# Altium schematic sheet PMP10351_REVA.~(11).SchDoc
size 431 x 279 mm; Date: Not shown in title block; ApprovedBy: Not shown in title block; CheckedBy: Not shown in title block; Author: Not shown in title block; CompanyName: Not shown in title block; Engineer: Not shown in title block; Organization: Not shown in title block; Address1: Not shown in title block; Address2: Not shown in title block; Address3: Not shown in title block; Address4: Not shown in title block; DocumentNumber: 1; Revision: Use project parameter SCH_Rev; SheetNumber: 1; SheetTotal: 1; PageSetup: Record=PageOptions|CenterHorizontal=True|CenterVertical=True|PrintScale=1.00|XCorrection=1.00|YCorrection=1.00|PrintKind=0|BorderSize=5000000|LeftOffset=0|BottomOffset=0|Orientation=2|PaperLength=1000|PaperWidth=1000|Scale=100|PaperSource=15|PrintQuality=600|MediaType=1|DitherType=10|PaperKind=Letter|PrintScaleMode=1
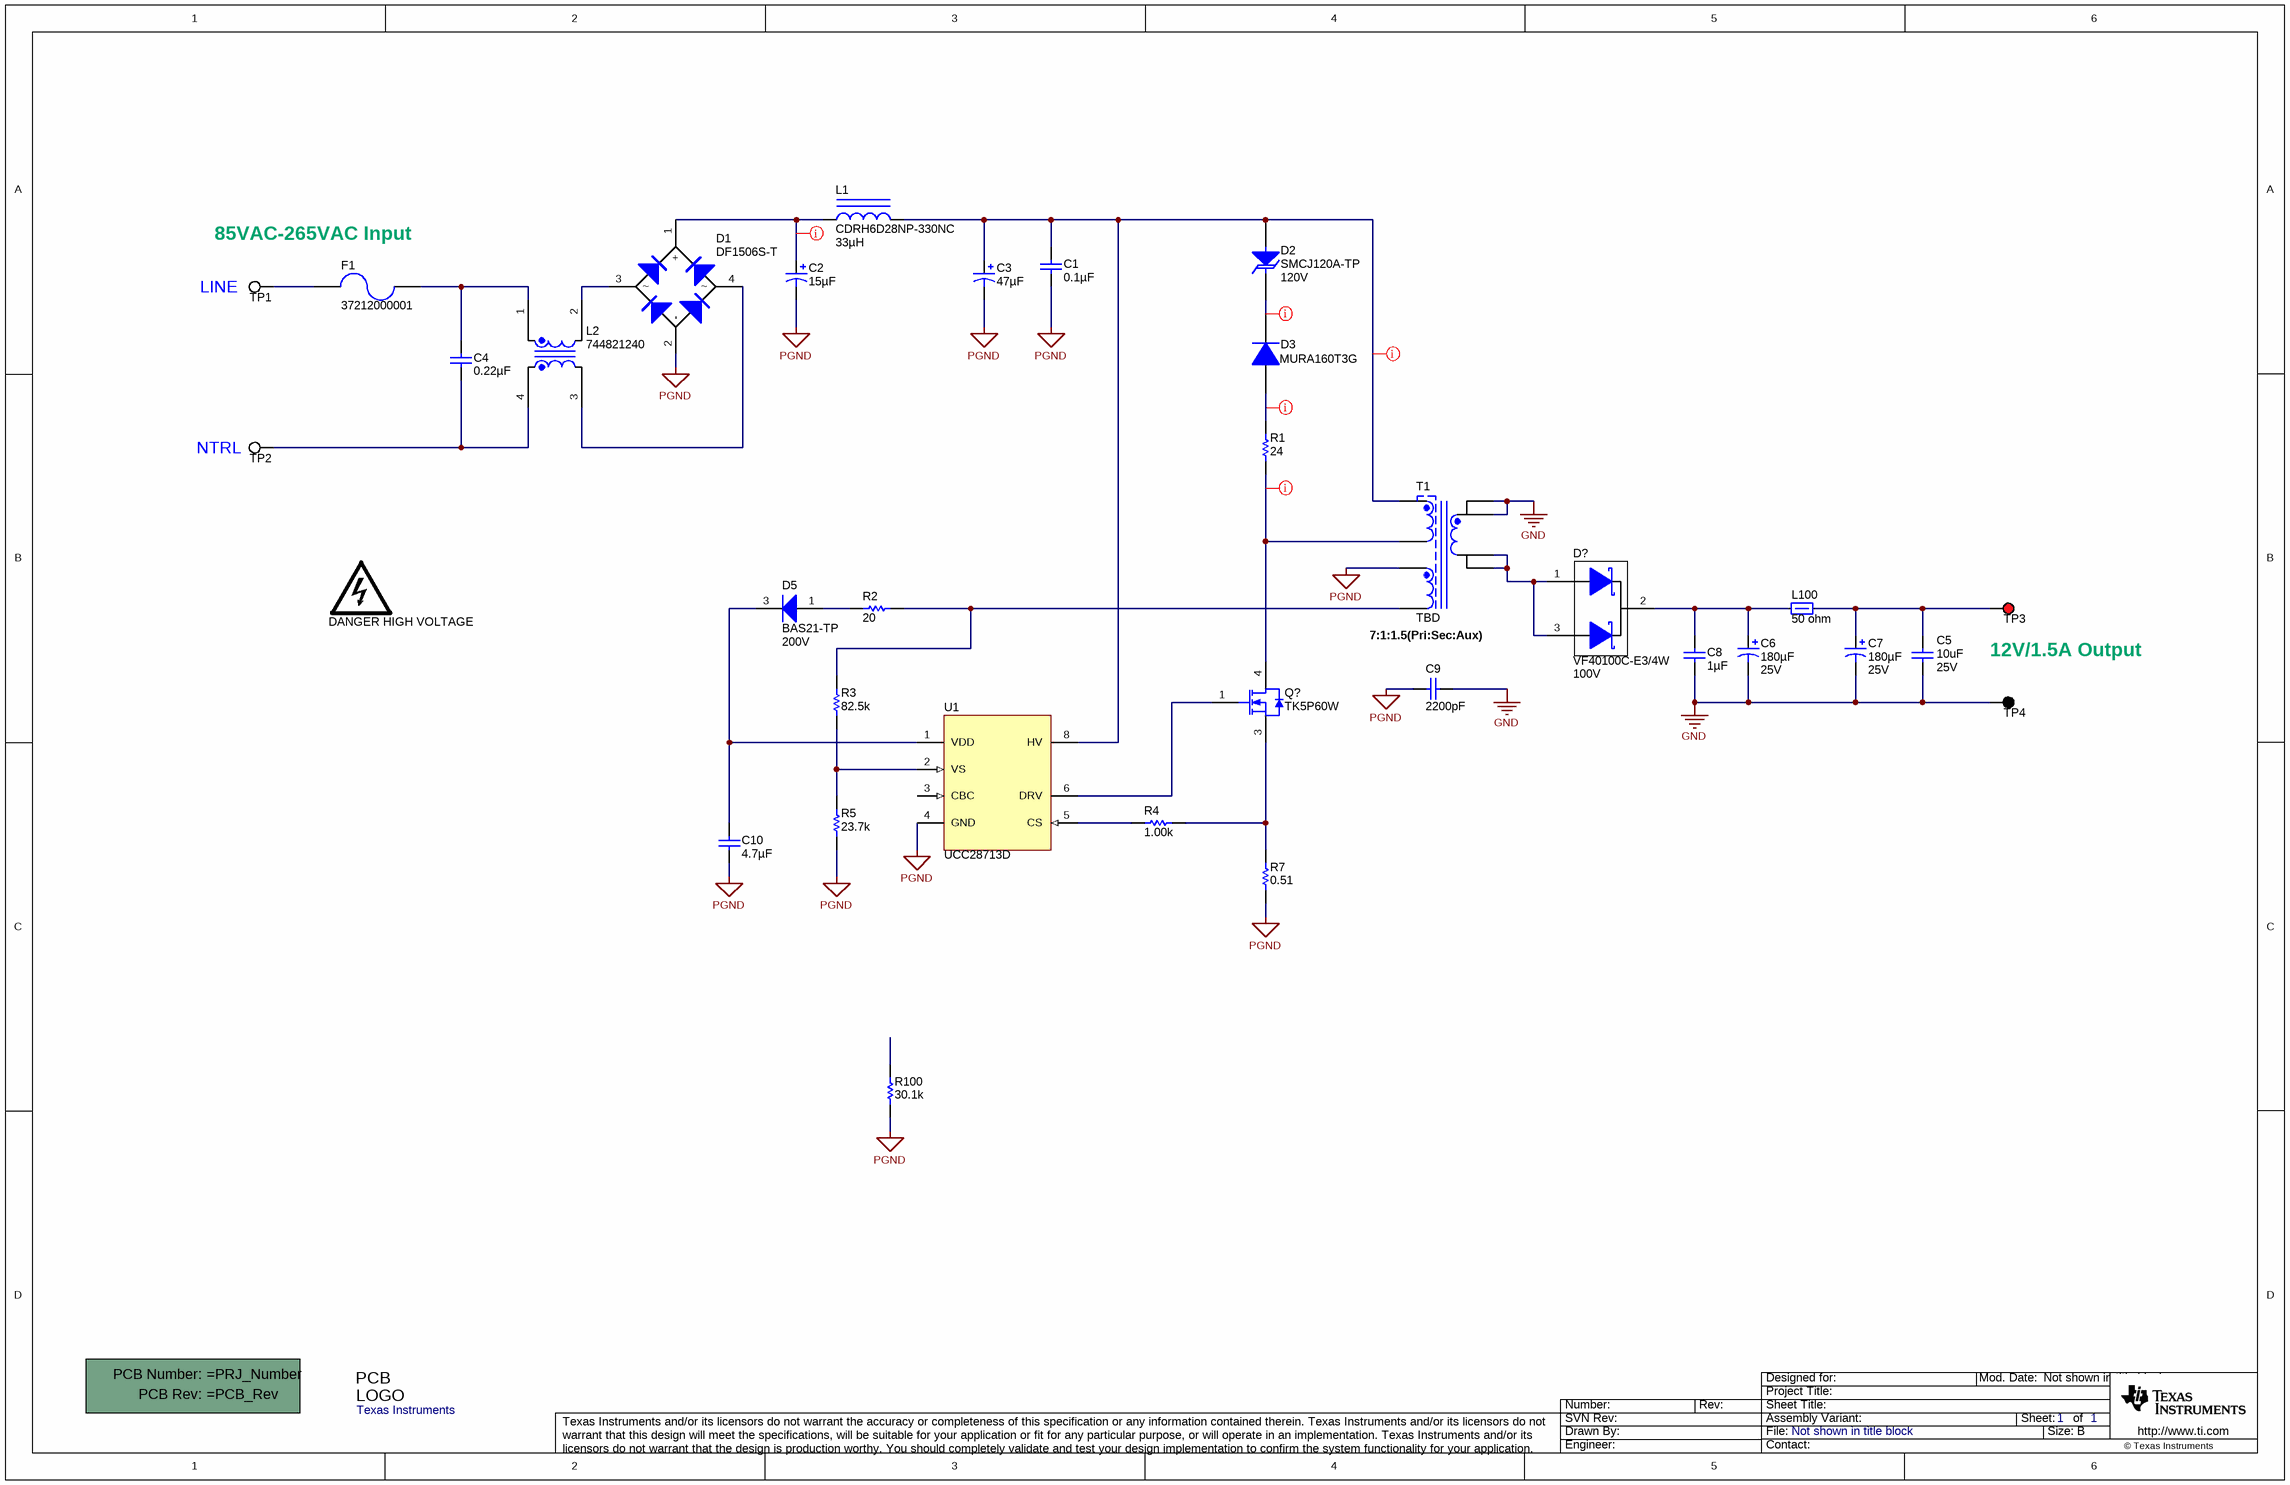
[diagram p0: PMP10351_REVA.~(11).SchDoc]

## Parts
(Parts that share a designator on the sheet are numbered #1, #2 ... from top to bottom, then left to right.)
!PCB  Printed Circuit Board  (value not drawn)  (mechanical)
C1  ValueDisplayed: 0.1µF  [1808_L]  (hidden comment: VJ1808Y104KXPAT5Z)
C2  ValueDisplayed: 15µF  [CAPPR5-12.5X20]  (hidden comment: EEUED2G150)
C3  ValueDisplayed: 47µF  [CAPPR7.5-18X20]  (hidden comment: EEUED2G470S)
C4  ValueDisplayed: 0.22µF  [B32922_12.5mm]  (hidden comment: B32922C3224M)
C5  value 10uF  Value2: 25V  [1206L]  (hidden comment: STD)
C6  ValueDisplayed: 180µF  Value2: 25V  [CAPPRD350W60D800H1150]  (hidden comment: 25SEPF180M)
C7  ValueDisplayed: 180µF  Value2: 25V  [CAPPRD350W60D800H1150]  (hidden comment: 25SEPF180M)
C8  ValueDisplayed: 1µF  [0603L]  (hidden comment: GRM188R61E105KA12D)
C9  ValueDisplayed: 2200pF  [CAPRD500W60D800H850]  (hidden comment: DE2E3KY222MA2BM01)
C10  ValueDisplayed: 4.7µF  [1206L]  (hidden comment: GRM319R61H475KA12)
D1  DF1506S-T  [DF-S]
D2  SMCJ120A-TP  value 120V  [SMC]
D3  MURA160T3G  [SMA]
D5  BAS21-TP  value 200V  [SOT-23L]
D?  VF40100C-E3/4W  value 100V  [TO-220AB]
F1  37212000001  [FUSE_372]
L1  CDRH6D28NP-330NC  ValueDisplayed: 33µH  [CDRH6D28]
L2  744821240  [WE-CMB_XS]
L100  value 50 ohm  [1206L]  (hidden comment: HI1206T500R-10)
LOGO1#1  DANGER HIGH VOLTAGE  [IEC_HighVoltage_Small]  (no BOM)
Logo1#2  Texas Instruments  [TI_Stacked_SolderMask_Small]  (no BOM)
Q?  TK5P60W  [DPAK]
R1  value 24  [2010L]  (hidden comment: CRCW201024R0JNEF)
R2  ValueDisplayed: 20  [0603L]  (hidden comment: CRCW060320R0JNEA)
R3  ValueDisplayed: 82.5k  [0402L]  (hidden comment: CRCW040282K5FKED)
R4  ValueDisplayed: 1.00k  [0402L]  (hidden comment: CRCW04021K00FKED)
R5  ValueDisplayed: 23.7k  [0402L]  (hidden comment: CRCW040223K7FKED)
R7  value 0.51  [0805L]  (hidden comment: CRM0805-FX-R510ELF)
R100  value 30.1k  [0603L]  (hidden comment: STD)
T1  TBD  [GCI_G134044LF]
TP1  5012  [Keystone5012]  (value not drawn)
TP2  5012  [Keystone5012]  (value not drawn)
TP3  5010  [Keystone5010]  (value not drawn)
TP4  5011  [Keystone5011]  (value not drawn)
U1  UCC28713D  [D0007A_L]

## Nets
GND: C5.2 C6.2(-) C7.2(-) C8.2 C9.1 T1.6 T1.7 TP4.1
PGND: C1.2 C2.2(-) C3.2(-) C9.2 C10.2 D1.2(-) R5.1 R7.1 R100.1 T1.1 U1.4(GND)
NetC1_1: C1.1 C3.1(+) D2.2(A) L1.2 T1.4 U1.8(HV)
NetC2_1: C2.1(+) D1.1(+) L1.1
NetC4_1: C4.1 F1.1 L2.1
NetC4_2: C4.2 L2.4 TP2.1
NetC5_1: C5.1 C7.1(+) L100.2 TP3.1
NetC6_1: C6.1(+) C8.1 D?.2(K) L100.1
NetC10_1: C10.1 D5.3(K) U1.1(VDD)
NetD1_3: D1.3 L2.2
NetD1_4: D1.4 L2.3
NetD2_1: D2.1(K) D3.1(K)
NetD3_2: D3.2(A) R1.2
NetD5_1: D5.1(A) R2.2
NetD?_1: D?.1(A) D?.3(A) T1.9 T1.10
NetF1_2: F1.2 TP1.1
NetQ?_1: Q?.1(G) U1.6(DRV)
NetQ?_3: Q?.3(S) R4.1 R7.2
NetQ?_4: Q?.4(D) R1.1 T1.5
NetR2_1: R2.1 R3.2 T1.2
NetR3_1: R3.1 R5.2 U1.2(VS)
NetR4_2: R4.2 U1.5(CS)

Not connected (* = marked no-connect by the designer): R100 2; U1 3(CBC)

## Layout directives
rule Clearance Constraint [Clearance = 24mil]: NetQ?_4
rule Clearance Constraint [Clearance = 25mil]: NetC1_1, NetC2_1, NetD2_1, NetD3_2

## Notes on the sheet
- 85VAC-265VAC Input
- (near TP1) LINE
- (near TP2) NTRL
- (near T1) 7:1:1.5(Pri:Sec:Aux)
- 12V/1.5A Output

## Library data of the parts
!PCB = PCB: Manufacturer: Any; SymbolCreator: a0412235
C1 = VJ1808Y104KXPAT5Z: CAP, CERM, 0.1uF, 250V, +/-10%, X7R, 1808; Manufacturer: Vishay-Vitramon; Polarized: N; CompType: Capacitor; U/M: EA; Cap_F: 0.0000001; Tolerance_%: 10; Value1: Unknown; VDC_V: 250; TaMin_C: -55; TaMax_C: 125; Cap_Case: 1808
C2 = EEUED2G150: CAP, AL, 15uF, 400V, +/-20%, 1.909859 ohm, TH; Manufacturer: Panasonic; Polarized: Y; CompType: Capacitor; U/M: EA; Cap_F: 0.000015; Tolerance_%: 20; VDC_V: 400; IRMS_A: 0.41; TaMin_C: -25; TaMax_C: 105; AC_Derating: 0.3
C3 = EEUED2G470S: CAP, AL, 47uF, 400V, +/-20%, 0.609529 ohm, TH; Manufacturer: Panasonic; Polarized: Y; CompType: Capacitor; U/M: EA; Cap_F: 0.000047; Tolerance_%: 20; VDC_V: 400; IRMS_A: 0.84; TaMin_C: -25; TaMax_C: 105; AC_Derating: 0.3
C4 = B32922C3224M: CAP, Film, 0.22uF, 630V, +/-20%, TH; Manufacturer: EPCOS Inc; Polarized: N; CompType: Capacitor; U/M: EA; Cap_F: 0.00000022; Tolerance_%: 20; Value1: Unknown; VDC_V: 630; TaMax_C: 110
C5 = C1206C103K5RACTU: CAP, CERM, 25V, +/-10%, X5R, 1206; Polarized: N; CompType: Capacitor; ValueDisplayed: 0.01µF; U/M: EA; Cap_F: 0.00000001; Tolerance_%: 10; ESR_Ohm: 0.155; Value1: 0.155 ohm; VDC_V: 50; TempCo: X7R; IRMS_A: 0.416; TaMin_C: -55; TaMax_C: 125; Cap_Case: 1206
C6 C7 = 200LLE10MEFC8X11.5: CAP ALUM 180UF 25V 20% RADIAL; Manufacturer: Panasonic; Polarized: Y; CompType: Capacitor; U/M: EA; Cap_F: 0.00001; Tolerance_%: 20; Value1: Unknown; VDC_V: 200; IRMS_A: 0.08; TaMin_C: -40; TaMax_C: 105; Cap_Case: Radial 8x11.5mm
C8 = GRM188R61E105KA12D: CAP, CERM, 1 µF, 25 V, +/- 10%, X5R, 0603; Manufacturer: MuRata; Polarized: N; CompType: Capacitor; Value: 1uF; U/M: EA; Cap_F: 0.000001; Tolerance_%: 10; Value1: Unknown; VDC_V: 25; Value2: 25V; TaMin_C: -55; TaMax_C: 85; Cap_Case: 0603
C9 = DE2E3KY222MA2BM01: CAP, CERM, 2200pF, 250V, +/-20%, KY, Radial D8x5mm; Manufacturer: MuRata; Polarized: N; CompType: Capacitor; U/M: EA; Cap_F: 0.0000000022; Tolerance_%: 20; Value1: Unknown; VDC_V: 250; TaMin_C: -25; TaMax_C: 85
C10 = GRM319R61H475KA12: CAP, CERM, 4.7 µF, 50 V, +/- 10%, X5R, 1206; Manufacturer: MuRata; Polarized: N; CompType: Capacitor; Value: 4.7uF; U/M: EA; Cap_F: 0.0000047; Tolerance_%: 10; Value1: Unknown; VDC_V: 50; Value2: 50V; TaMin_C: -55; TaMax_C: 85; Cap_Case: 1206
D1 = DF1506S-T: Diode, Switching-Bridge, 600V, 1.5A, DF-S; Manufacturer: Diodes Inc.; Value: 1.1V; U/M: EA; Vf_V: 1.1; Io_A: 1.5; Vr_V: 600; TJmax_C: 150
D2 = SMCJ120A-TP: Diode, TVS, Uni, 120V, 1500W, SMC; Manufacturer: Micro Commercial Components; U/M: EA; Power_W: 1500; Vr_V: 120
D3 = MURA160T3G: Diode, Ultrafast, 600V, 1A, SMA; Manufacturer: ON Semiconductor; Value: 1.05V; U/M: EA; Vf_V: 1.05; Io_A: 1; Vr_V: 600; TJmax_C: 175
D5 = BAS21-TP: Diode, P-N, 200V, 200A, SOT-23; Manufacturer: Micro Commercial Components; U/M: EA; Vf_V: 1.25; Io_A: 200; Value2: 1.25V; TJmax_C: 150; RJC_CperW: 430
D? = VF40100C-E3/4W: Diode, Schottky, 100V, 20A, TH; Manufacturer: Vishay-Semiconductor; SymbolCreator: a0411947; U/M: EA; Vf_V: 0.73; Value2: 0.73V; Io_A: 20; Vr_V: 100; TJmax_C: 150; RJC_CperW: 2
F1 = 37215000001: Fuse, 2A, 250V, TH; Manufacturer: Littelfuse; U/M: EA; OpeningTime_100%_min: 4; OpeningTime_200%_max: 2; VDC_V: 250; Irating_A: 5; MeltingTyp: 94; Vdrop: 0.08; Soldering_Wave_MaxTemp_C: 260
L1 = CDRH6D28NP-330NC: Inductor, Shielded Drum Core, Ferrite, 33uH, 0.97A, 0.165 ohm, SMD; Manufacturer: Sumida; Ind_H: 33.0E-6; Imax_A: 0.97; Irms: 0.97A @ 30C rise; Isat: 0.97A @ 35% inductance drop; DCR_ohm: 0.165; U/M: EA
L2 = 744821240: Coupled inductor, 4000uH, 1.5A, 0.14 ohm, +/-30%, TH; Manufacturer: Wurth Elektronik eiSos; SymbolCreator: a0412235; Ind_H: 0.004; DCR_Ohm: 0.14; Isat: 1.5; Tolerance_%: 30; U/M: EA
L100 = HI1206T500R-10: 6A Ferrite Bead, 50 ohm @ 100MHz, SMD; Manufacturer: Steward; Imax_A: 6; DCR_ohm: 0.01; Value1: 0.01 ohm; ZTyp@100MHz_Ohm: 50; Ztyp@1GHz_Ohm: 70; U/M: EA
LOGO1#1 = IEC_HighVoltage: IEC 61010-1 High Voltage Warning; SymbolCreator: a0412235
Logo1#2 = TI_Logo: Texas Instrument Corporate Signature; SymbolCreator: a0412235
Q? = STD13NM60N: MOSFET N CH 600V 5.4A DPAK; Manufacturer: Toshiba; Alternate Manufacturer: None; U/M: EA; Value: 650V; VdsMax_V: 650; Value1: 0.36 ohm; Rdson45_Ohm: 0.36; Value2: 30 nC; QgTyp_nC: 30; Vgs_V: 4; IdsMax_A: 11
R1 = CRCW201024R0JNEF: RES, 24 ohm, 5%, 0.75W, 2010; Manufacturer: Vishay-Dale; CompType: Resistor; Value_Code: 24R0; Tolerance_%: 5; Power_W: 0.75; VDC_V: 400; TempCo: 200 ppm/C; EIA_Code: E24; U/M: EA
R2 = CRCW060320R0JNEA: RES, 20, 5%, 0.1 W, 0603; Manufacturer: Vishay-Dale; CompType: Resistor; Value: 20; Value_Code: 20R0; Tolerance_%: 5; Power_W: 0.1; Value2: 0.1W; VDC_V: 75; TempCo: 200 ppm/C; EIA_Code: E24; U/M: EA
R3 = CRCW040282K5FKED: RES, 82.5 k, 1%, 0.063 W, 0402; Manufacturer: Vishay-Dale; CompType: Resistor; Value: 82.5k; Res_ohm: 82500; Value_Code: 82k5; Tolerance_%: 1; Power_W: 0.063; Value2: 0.063W; VDC_V: 50; TempCo: 100 ppm/C; EIA_Code: E96; U/M: EA
R4 = CRCW04021K00FKED: RES, 1.00 k, 1%, 0.063 W, 0402; Manufacturer: Vishay-Dale; CompType: Resistor; Value: 1.00k; Res_ohm: 1000; Value_Code: 1k00; Tolerance_%: 1; Power_W: 0.063; Value2: 0.063W; VDC_V: 50; TempCo: 100 ppm/C; EIA_Code: E96; U/M: EA
R5 = CRCW040223K7FKED: RES, 23.7 k, 1%, 0.063 W, 0402; Manufacturer: Vishay-Dale; CompType: Resistor; Value: 23.7k; Res_ohm: 23700; Value_Code: 23k7; Tolerance_%: 1; Power_W: 0.063; Value2: 0.063W; VDC_V: 50; TempCo: 100 ppm/C; EIA_Code: E96; U/M: EA
R7 = CRM0805-FX-R510ELF: RES, 0.51 ohm, 1%, 0.25W, 0805; Manufacturer: Bourns; CompType: Resistor; Value_Code: R510; Tolerance_%: 1; Power_W: 0.25; VDC_V: 0; TempCo: 100 ppm/C; EIA_Code: E96; U/M: EA
R100 = CRCW06030000Z0EA: RES,  1%, 0.1W, 0603; CompType: Resistor; Res_ohm: 0; Value_Code: 0000; Tolerance_%: 5; Value1: 5%; Power_W: 0.1; VDC_V: 75; TempCo: 200 ppm/C; EIA_Code: E24; U/M: EA
T1 = G134044LF: Transformer, 400uH, TH; SymbolCreator: a0411947; DCR_Ohm: 1.25; LeakageL: 4.5uH; U/M: EA
TP1 TP2 = 5012: Test Point, Multipurpose, White, TH; Manufacturer: Keystone; CompType: Test Point Loop; U/M: EA
TP3 = 5010: Test Point, Multipurpose, Red, TH; Manufacturer: Keystone; CompType: Test Point Loop; U/M: EA
TP4 = 5011: Test Point, Multipurpose, Black, TH; Manufacturer: Keystone; CompType: Test Point Loop; U/M: EA
U1 = UCC28710D: Constant-Voltage, Constant-Current Controller With Primary-Side Regulation, D0007A; Alternate Manufacturer: None; Manufacturer: Texas Instruments; SymbolCreator: a0411947; CompType: IC; U/M: EA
